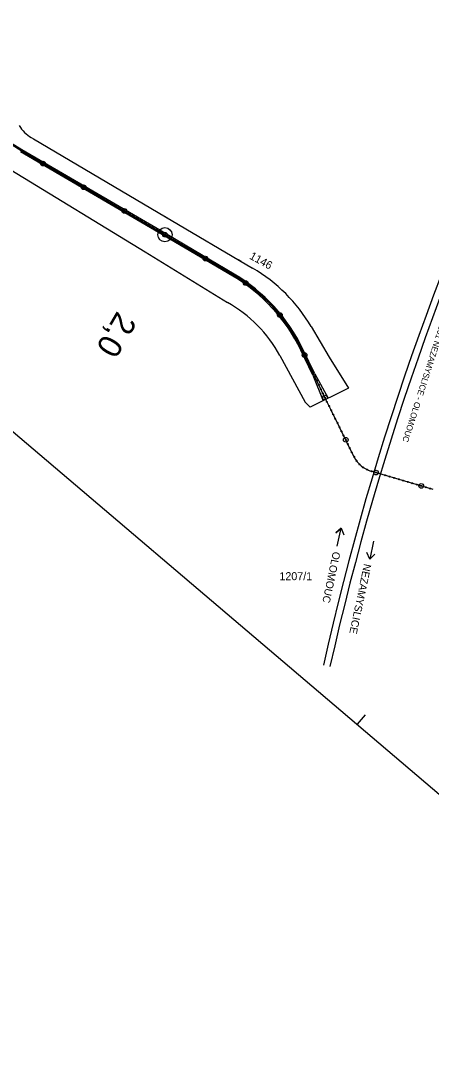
# Model space of a CAD drawing. Extents: x -548552 to -543113, y -1131925 to -1123599.
# Drawn here: x -548076.9 to -547989.6, y -1125238.7 to -1125021.3 of the extents above; entities that cross this region are included whole.
import ezdxf

# ---------------------------------------------------------------- set-up
doc = ezdxf.new("R2010")
doc.units = 0
for name, color, linetype in [('HRANY', 7, 'Continuous'), ('Parcelní čísla', 7, 'Continuous'), ('Poz předměty', 7, 'Continuous'), ('Profile', 7, 'Continuous'), ('PROFILY NÁVRH', 7, 'Continuous'), ('STANIČENÍ', 7, 'Continuous'), ('ŽELEZNICE', 7, 'Continuous')]:
    doc.layers.add(name, color=color, linetype=linetype)

msp = doc.modelspace()

# ---------------------------------------------------------------- linework, layer by layer
at = {"layer": 'HRANY'}
msp.add_line((-548016.41, -1125102.29), (-548015.37, -1125103.38), dxfattribs=at)
at = {"layer": 'Profile'}
for p, q in [((-548104.58, -1125086.4), (-548015.02, -1125162.57)), ((-548104.58, -1125086.4), (-548015.02, -1125162.57)), ((-548015.02, -1125162.57), (-547925.45, -1125238.74)), ((-548015.02, -1125162.57), (-547925.45, -1125238.74)), ((-548015.02, -1125162.57), (-547925.45, -1125238.74)), ((-548003.72, -1125168.7), (-548005.43, -1125170.72))]:
    msp.add_line(p, q, dxfattribs=at)
at = {"layer": 'PROFILY NÁVRH'}
for p, q in [((-548076.64, -1125048.71), (-548094.17, -1125037.91)), ((-548074.61, -1125046.13), (-548074.14, -1125046.4)), ((-548074.14, -1125046.4), (-548046.1, -1125062.96)), ((-548047.56, -1125066.26), (-548076.9, -1125049.14)), ((-548047.3, -1125065.82), (-548076.65, -1125048.7)), ((-548078.92, -1125052.96), (-548050.45, -1125070.42)), ((-548046.1, -1125062.96), (-548027.59, -1125073.85)), ((-548031.52, -1125075.13), (-548047.3, -1125065.82)), ((-548031.77, -1125075.56), (-548047.56, -1125066.26)), ((-548050.45, -1125070.42), (-548032.93, -1125081.17)), ((-548015.15, -1125086.28), (-548011.32, -1125092.79)), ((-548014.83, -1125096.55), (-548017.38, -1125091.24)), ((-548014.38, -1125096.33), (-548016.93, -1125091.03)), ((-548021.81, -1125092.42), (-548016.41, -1125102.29)), ((-548011.32, -1125092.79), (-548007.25, -1125099.37)), ((-548014.83, -1125096.55), (-548012.6, -1125102.01)), ((-548014.38, -1125096.33), (-548011.53, -1125101.48)), ((-548007.25, -1125099.37), (-548015.37, -1125103.38))]:
    msp.add_line(p, q, dxfattribs=at)
msp.add_circle((-548046.22, -1125066.75), 1.5, dxfattribs=at)
for centre, radius, start, end in [((-548071.2, -1125040.2), 6.84, 209.418, 240.1292), ((-548045.38, -1125104.09), 35.09, 30.5087, 59.5384), ((-548047.06, -1125106.25), 28.79, 28.7108, 60.5965)]:
    msp.add_arc(centre, radius, start, end, dxfattribs=at)
for major_axis, ratio in [((-27.18, 24.37), 0.998278), ((-27.55, 24.71), 0.998301)]:
    msp.add_ellipse((-548050.27, -1125106.97), major_axis=major_axis, ratio=ratio, start_param=4.319306, end_param=4.910911, dxfattribs=at)
at = {"layer": 'STANIČENÍ'}
for p, q in [((-548076.78, -1125048.92), (-548094.3, -1125038.12)), ((-548047.43, -1125066.04), (-548076.78, -1125048.92)), ((-548045.75, -1125063.16), (-548046.41, -1125062.78)), ((-548031.65, -1125075.35), (-548047.43, -1125066.04)), ((-548029.94, -1125072.46), (-548030.59, -1125072.08)), ((-548012.14, -1125101.6), (-548017.15, -1125091.14)), ((-548012.06, -1125101.74), (-548012.14, -1125101.6)), ((-548010.85, -1125104.19), (-548012.06, -1125101.74)), ((-548006.02, -1125113.98), (-548010.85, -1125104.19))]:
    msp.add_line(p, q, dxfattribs=at)
msp.add_lwpolyline([(-547989.22, -1125120.86), (-548002.48, -1125116.95)], dxfattribs=at)
for centre, radius in [((-548076.45, -1125049.11), 0.1), ((-548075.59, -1125049.61), 0.1), ((-548074.72, -1125050.12), 0.1), ((-548073.86, -1125050.62), 0.1), ((-548073, -1125051.12), 0.1), ((-548072.13, -1125051.63), 0.5), ((-548072.13, -1125051.63), 0.1), ((-548071.27, -1125052.13), 0.1), ((-548070.4, -1125052.64), 0.1), ((-548069.54, -1125053.14), 0.1), ((-548068.68, -1125053.64), 0.1), ((-548067.81, -1125054.15), 0.1), ((-548066.95, -1125054.65), 0.1), ((-548066.09, -1125055.16), 0.1), ((-548065.22, -1125055.66), 0.1), ((-548064.36, -1125056.16), 0.1), ((-548063.49, -1125056.67), 0.5), ((-548063.49, -1125056.67), 0.1), ((-548062.63, -1125057.17), 0.1), ((-548061.77, -1125057.68), 0.1), ((-548060.9, -1125058.18), 0.1), ((-548060.04, -1125058.68), 0.1), ((-548059.18, -1125059.19), 0.1), ((-548058.31, -1125059.69), 0.1), ((-548057.45, -1125060.2), 0.1), ((-548056.58, -1125060.7), 0.1), ((-548055.72, -1125061.2), 0.1), ((-548054.86, -1125061.71), 0.5), ((-548054.86, -1125061.71), 0.1), ((-548053.99, -1125062.21), 0.1), ((-548053.13, -1125062.71), 0.1), ((-548052.27, -1125063.22), 0.1), ((-548051.4, -1125063.72), 0.1), ((-548050.54, -1125064.23), 0.1), ((-548049.67, -1125064.73), 0.1), ((-548048.81, -1125065.23), 0.1), ((-548047.95, -1125065.74), 0.1), ((-548047.08, -1125066.24), 0.1), ((-548046.22, -1125066.75), 0.5), ((-548046.22, -1125066.75), 0.1), ((-548045.36, -1125067.26), 0.1), ((-548044.5, -1125067.77), 0.1), ((-548043.64, -1125068.28), 0.1), ((-548042.78, -1125068.78), 0.1), ((-548041.92, -1125069.29), 0.1), ((-548041.06, -1125069.8), 0.1), ((-548040.19, -1125070.31), 0.1), ((-548039.33, -1125070.82), 0.1), ((-548038.47, -1125071.32), 0.1), ((-548037.61, -1125071.83), 0.5), ((-548037.61, -1125071.83), 0.1), ((-548036.75, -1125072.34), 0.1), ((-548035.89, -1125072.85), 0.1), ((-548035.03, -1125073.36), 0.1), ((-548034.16, -1125073.86), 0.1), ((-548033.3, -1125074.37), 0.1), ((-548032.44, -1125074.88), 0.1), ((-548031.58, -1125075.39), 0.1), ((-548030.73, -1125075.91), 0.1), ((-548029.89, -1125076.45), 0.1), ((-548029.07, -1125077.02), 0.5), ((-548029.07, -1125077.02), 0.1), ((-548028.26, -1125077.61), 0.1), ((-548027.47, -1125078.22), 0.1), ((-548026.69, -1125078.85), 0.1), ((-548025.93, -1125079.5), 0.1), ((-548025.19, -1125080.18), 0.1), ((-548024.47, -1125080.87), 0.1), ((-548023.77, -1125081.58), 0.1), ((-548023.09, -1125082.31), 0.1), ((-548022.43, -1125083.06), 0.1), ((-548021.79, -1125083.83), 0.5), ((-548021.79, -1125083.83), 0.1), ((-548021.17, -1125084.61), 0.1), ((-548020.57, -1125085.42), 0.1), ((-548019.99, -1125086.23), 0.1), ((-548019.44, -1125087.06), 0.1), ((-548018.9, -1125087.91), 0.1), ((-548018.4, -1125088.77), 0.1), ((-548017.91, -1125089.65), 0.1), ((-548017.45, -1125090.53), 0.1), ((-548017.01, -1125091.43), 0.1), ((-548016.58, -1125092.33), 0.5), ((-548016.58, -1125092.33), 0.1), ((-548016.15, -1125093.24), 0.1), ((-548015.71, -1125094.14), 0.1), ((-548015.28, -1125095.04), 0.1), ((-548014.85, -1125095.94), 0.1), ((-548014.42, -1125096.84), 0.1), ((-548013.98, -1125097.74), 0.1), ((-548013.55, -1125098.64), 0.1), ((-548013.12, -1125099.55), 0.1), ((-548012.69, -1125100.45), 0.1), ((-548012.26, -1125101.35), 0.5), ((-548012.26, -1125101.35), 0.1), ((-548011.82, -1125102.25), 0.1), ((-548011.37, -1125103.14), 0.1), ((-548010.93, -1125104.04), 0.1), ((-548010.49, -1125104.93), 0.1), ((-548010.04, -1125105.83), 0.1), ((-548009.6, -1125106.73), 0.1), ((-548009.16, -1125107.62), 0.1), ((-548008.72, -1125108.52), 0.1), ((-548008.27, -1125109.41), 0.1), ((-548007.83, -1125110.31), 0.5), ((-548007.83, -1125110.31), 0.1), ((-548007.39, -1125111.21), 0.1), ((-548006.94, -1125112.1), 0.1), ((-548006.5, -1125113), 0.1), ((-548006.06, -1125113.9), 0.1), ((-548005.55, -1125114.76), 0.1), ((-548004.91, -1125115.52), 0.1), ((-548004.14, -1125116.16), 0.1), ((-548003.27, -1125116.65), 0.1), ((-548002.34, -1125117), 0.1), ((-548001.38, -1125117.28), 0.5), ((-548001.38, -1125117.28), 0.1), ((-548000.42, -1125117.56), 0.1), ((-547999.46, -1125117.84), 0.1), ((-547998.5, -1125118.13), 0.1), ((-547997.54, -1125118.41), 0.1), ((-547996.58, -1125118.69), 0.1), ((-547995.62, -1125118.98), 0.1), ((-547994.66, -1125119.26), 0.1), ((-547993.7, -1125119.54), 0.1), ((-547992.74, -1125119.82), 0.1), ((-547991.78, -1125120.11), 0.5), ((-547991.78, -1125120.11), 0.1), ((-547990.83, -1125120.39), 0.1), ((-547989.87, -1125120.67), 0.1)]:
    msp.add_circle(centre, radius, dxfattribs=at)
for centre, major_axis, ratio, start_param, end_param in [((-548050.27, -1125106.97), (-27.37, 24.54), 0.99829, 4.319306, 4.910911), ((-548000.85, -1125111.43), (-5.48, 1.79), 0.999048, 0.774252, 1.599902)]:
    msp.add_ellipse(centre, major_axis=major_axis, ratio=ratio, start_param=start_param, end_param=end_param, dxfattribs=at)
at = {"layer": 'ŽELEZNICE'}
for points in [[(-548009.62, -1125132.87), (-548008.81, -1125129.05), (-548009.95, -1125130.1), (-548008.81, -1125129.05), (-548008.22, -1125130.51)], [(-548001.94, -1125131.85), (-548002.74, -1125135.66), (-548001.61, -1125134.61), (-548002.74, -1125135.66), (-548003.33, -1125134.21)]]:
    msp.add_lwpolyline(points, dxfattribs=at)
for radius in [585.63, 584.19]:
    msp.add_arc((-547441, -1125285.7), radius, 153.15591, 167.4209, dxfattribs=at)

# ---------------------------------------------------------------- texts
at = {"layer": 'Parcelní čísla'}
msp.add_text('1146', height=1.7, rotation=331.3075, dxfattribs=at).set_placement((-548028.43, -1125071.77))
msp.add_text('1207/1', height=1.7, dxfattribs=at).set_placement((-548021.91, -1125140.12))
at = {"layer": 'Poz předměty'}
msp.add_text('DRÁHA  ČD, TRAŤ 301 NEZAMYSLICE - OLOMOUC', height=1.28, rotation=252.3213, dxfattribs=at).set_placement((-547983.33, -1125071.4))
at = {"layer": 'STANIČENÍ'}
msp.add_text('2,0', height=5, rotation=239.7403, dxfattribs=at).set_placement((-548056.32, -1125082.78))
at = {"layer": 'ŽELEZNICE'}
for s, p in [('OLOMOUC', (-548010.52, -1125133.96)), ('NEZAMYSLICE', (-548003.94, -1125136.55))]:
    msp.add_text(s, height=1.6, rotation=258.0816, dxfattribs=at).set_placement(p)

doc.saveas('drawing.dxf')
